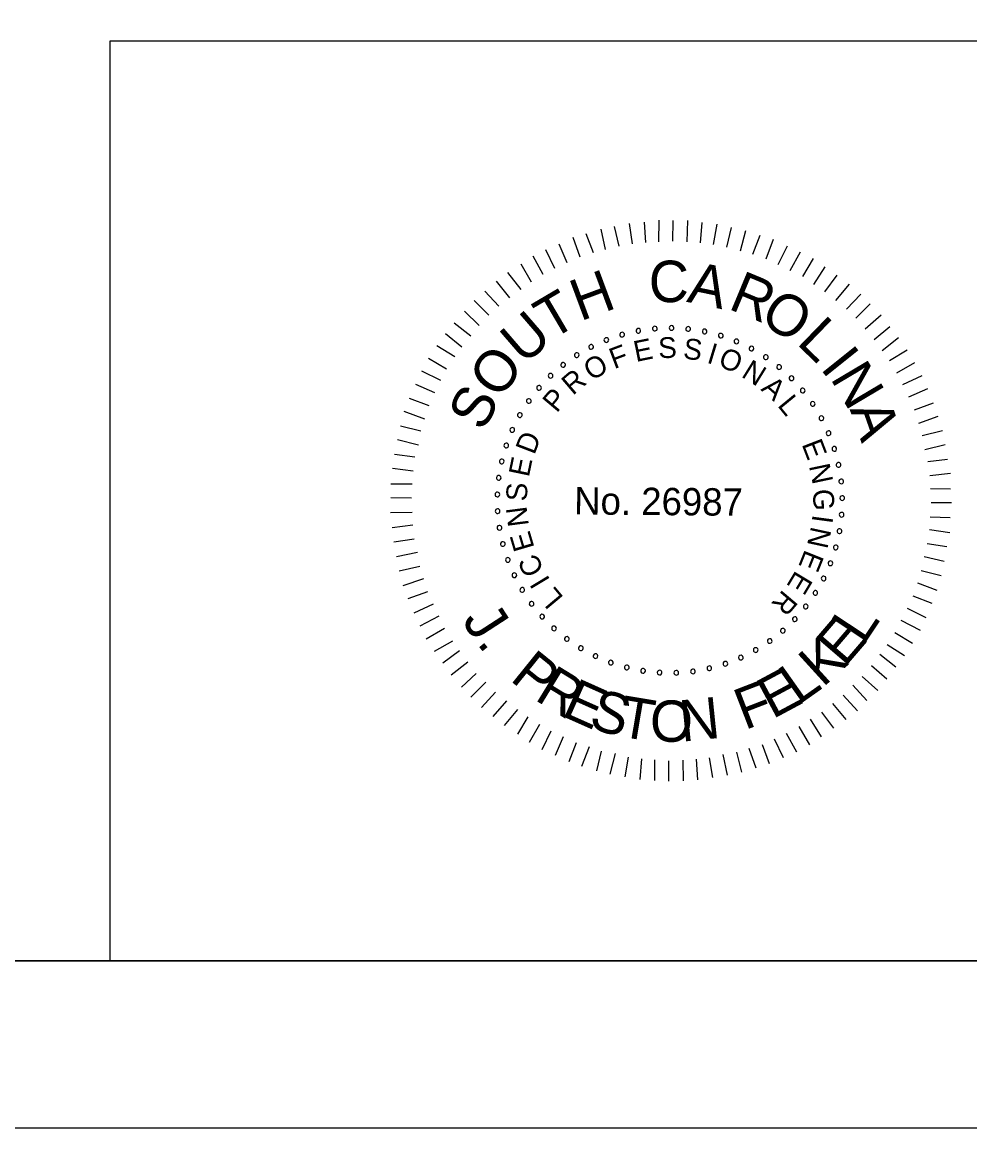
# Model space of a CAD drawing. Extents: x -125.5 to -89.4, y -5.1 to 16.9.
# Drawn here: x -103.162 to -100.328, y -5.066 to -1.76 of the extents above; entities that cross this region are included whole.
import ezdxf

# ---------------------------------------------------------------- set-up
doc = ezdxf.new("R2010")
doc.units = 0
for name, color, linetype in [('BR_BORDER LINES', 7, 'Continuous'), ('BR_TABLE LINES', 7, 'Continuous'), ('BR_TEXT', 7, 'Continuous'), ('Level 31', 7, 'Continuous')]:
    doc.layers.add(name, color=color, linetype=linetype)

msp = doc.modelspace()

# ---------------------------------------------------------------- linework, layer by layer
at = {"layer": 'BR_BORDER LINES'}
for p, q in [((-102.8989, -1.8161), (-97.5337, -1.8161)), ((-102.8989, -4.5661), (-102.8989, -1.8161)), ((-123.6994, -4.5662), (-90.0334, -4.5662))]:
    msp.add_line(p, q, dxfattribs=at)
at = {"layer": 'BR_TABLE LINES'}
msp.add_lwpolyline([(-123.6994, 16.4338), (-90.0334, 16.4338), (-90.0334, -4.5662), (-123.6994, -4.5662)], close=True, dxfattribs=at)
at = {"layer": 'BR_TEXT'}
for p, q in [((-101.418, -2.4404), (-101.4312, -2.3793)), ((-101.3767, -2.4304), (-101.3908, -2.3711)), ((-101.3372, -2.423), (-101.3461, -2.362)), ((-101.2977, -2.419), (-101.3015, -2.3581)), ((-101.2582, -2.4168), (-101.2576, -2.3524)), ((-101.2161, -2.4146), (-101.2156, -2.3528)), ((-101.1741, -2.4175), (-101.1718, -2.3531)), ((-101.1338, -2.4204), (-101.129, -2.3595)), ((-101.0952, -2.425), (-101.0844, -2.3642)), ((-101.0549, -2.4331), (-101.0407, -2.374)), ((-101.4937, -2.4629), (-101.5147, -2.4044)), ((-101.4541, -2.4504), (-101.476, -2.3927)), ((-101.0138, -2.4437), (-100.9979, -2.3829)), ((-100.977, -2.4543), (-100.9551, -2.397)), ((-100.9376, -2.4675), (-100.9157, -2.4093)), ((-101.5695, -2.4966), (-101.5957, -2.4406)), ((-101.5325, -2.4798), (-101.556, -2.4238)), ((-100.9017, -2.485), (-100.8738, -2.4294)), ((-101.604, -2.5144), (-101.6344, -2.46)), ((-100.8658, -2.5024), (-100.8345, -2.4469)), ((-100.8282, -2.5208), (-100.796, -2.467)), ((-101.6704, -2.5593), (-101.7095, -2.5083)), ((-101.6394, -2.5381), (-101.6698, -2.4838)), ((-100.795, -2.5451), (-100.761, -2.4913)), ((-101.7041, -2.5847), (-101.744, -2.5346)), ((-100.7617, -2.5668), (-100.7252, -2.5165)), ((-100.7293, -2.5928), (-100.6886, -2.5434)), ((-101.7369, -2.6094), (-101.7786, -2.5644)), ((-100.6977, -2.618), (-100.6545, -2.5737)), ((-101.7663, -2.6366), (-101.8106, -2.5925)), ((-100.6697, -2.6456), (-100.6264, -2.6022)), ((-101.7958, -2.6673), (-101.8392, -2.6248)), ((-100.6416, -2.6768), (-100.594, -2.6351)), ((-101.8209, -2.6988), (-101.8704, -2.6598)), ((-100.6144, -2.7088), (-100.5677, -2.6705)), ((-101.8469, -2.732), (-101.8964, -2.6922)), ((-100.5906, -2.7424), (-100.5414, -2.7033)), ((-101.8686, -2.761), (-101.9224, -2.728)), ((-100.5686, -2.7718), (-100.516, -2.7396)), ((-101.893, -2.7977), (-101.9467, -2.7656)), ((-101.9104, -2.8319), (-101.9668, -2.804)), ((-100.5466, -2.8089), (-100.4931, -2.7776)), ((-100.5288, -2.8433), (-100.4711, -2.8164)), ((-101.9279, -2.8687), (-101.9852, -2.8433)), ((-100.5111, -2.8804), (-100.4543, -2.856)), ((-101.9454, -2.9072), (-102.0035, -2.8852)), ((-100.4943, -2.9192), (-100.4374, -2.8982)), ((-101.9577, -2.9474), (-102.0193, -2.9246)), ((-100.4809, -2.9596), (-100.4232, -2.9378)), ((-101.97, -2.9833), (-102.0308, -2.9682)), ((-100.4708, -2.9957), (-100.4107, -2.9816)), ((-101.9772, -3.0253), (-102.0397, -3.0094)), ((-100.4626, -3.0378), (-100.4024, -3.0229)), ((-101.9878, -3.0613), (-102.0487, -3.0531)), ((-100.4543, -3.074), (-100.3951, -3.0667)), ((-101.9925, -3.1024), (-102.0542, -3.0951)), ((-100.4478, -3.1152), (-100.3868, -3.1088)), ((-101.9954, -3.1419), (-102.0597, -3.1414)), ((-100.4464, -3.1547), (-100.3863, -3.1552)), ((-101.9974, -3.183), (-102.06, -3.1825)), ((-100.4442, -3.1959), (-100.3833, -3.1964)), ((-101.9961, -3.226), (-102.0604, -3.2272)), ((-100.4471, -3.2388), (-100.3871, -3.241)), ((-101.9938, -3.2646), (-102.0556, -3.2718)), ((-101.9898, -3.3058), (-102.0509, -3.3148)), ((-100.4492, -3.2774), (-100.3883, -3.2856)), ((-100.4564, -3.3185), (-100.3972, -3.3284)), ((-101.9799, -3.3454), (-102.0426, -3.3586)), ((-100.4653, -3.3579), (-100.4053, -3.3721)), ((-101.9733, -3.3875), (-102.0344, -3.4016)), ((-100.4742, -3.3999), (-100.4143, -3.415)), ((-101.9616, -3.4245), (-102.0236, -3.4454)), ((-100.4848, -3.4367), (-100.4275, -3.4586)), ((-101.95, -3.4632), (-102.0085, -3.4842)), ((-101.9331, -3.5003), (-101.9908, -3.5272)), ((-100.4989, -3.4752), (-100.4424, -3.4971)), ((-101.9162, -3.5364), (-101.9731, -3.566)), ((-100.5163, -3.512), (-100.4599, -3.5399)), ((-100.5346, -3.5479), (-100.4774, -3.5784)), ((-101.8994, -3.5735), (-101.9537, -3.6048)), ((-100.553, -3.5846), (-100.5, -3.6168)), ((-101.8756, -3.6106), (-101.93, -3.6419)), ((-100.5756, -3.6213), (-100.5235, -3.6535)), ((-101.8544, -3.6399), (-101.9045, -3.6764)), ((-100.5981, -3.6503), (-100.5495, -3.6876)), ((-101.829, -3.6736), (-101.8791, -3.7127)), ((-100.6224, -3.6836), (-100.5764, -3.7234)), ((-101.8043, -3.7073), (-101.8485, -3.7481)), ((-101.7754, -3.7333), (-101.8204, -3.7784)), ((-100.6502, -3.7168), (-100.6033, -3.7584)), ((-101.7465, -3.7636), (-101.7889, -3.8095)), ((-100.6787, -3.7423), (-100.6362, -3.7882)), ((-101.714, -3.7895), (-101.7548, -3.8364)), ((-100.7392, -3.7976), (-100.6993, -3.8452)), ((-100.7073, -3.7721), (-100.6648, -3.8188)), ((-101.6808, -3.8156), (-101.7207, -3.8633)), ((-100.772, -3.8231), (-100.7364, -3.8714)), ((-101.6501, -3.8373), (-101.6814, -3.8894)), ((-101.6151, -3.8599), (-101.6464, -3.9137)), ((-100.8393, -3.8663), (-100.808, -3.9206)), ((-100.8057, -3.8443), (-100.7727, -3.8969)), ((-101.5809, -3.8799), (-101.608, -3.9355)), ((-101.5442, -3.8974), (-101.5687, -3.953)), ((-100.8773, -3.8857), (-100.8468, -3.9418)), ((-101.5057, -3.9149), (-101.5276, -3.9713)), ((-101.4663, -3.9272), (-101.4891, -3.9854)), ((-100.9892, -3.9311), (-100.9682, -3.9897)), ((-100.9496, -3.9194), (-100.9286, -3.9763)), ((-100.9135, -3.9026), (-100.8865, -3.9586)), ((-101.4304, -3.9395), (-101.4446, -3.9986)), ((-101.3892, -3.9467), (-101.4044, -4.0084)), ((-101.3499, -3.9582), (-101.3598, -4.0165)), ((-101.3104, -3.9628), (-101.3152, -4.0246)), ((-101.271, -3.9657), (-101.2715, -4.0275)), ((-101.1869, -3.9664), (-101.1857, -4.0282)), ((-101.1466, -3.9642), (-101.1428, -4.026)), ((-101.1079, -3.9602), (-101.098, -4.0186)), ((-101.0675, -3.9494), (-101.0542, -4.0113)), ((-101.0262, -3.9429), (-101.0112, -4.0022)), ((-101.229, -3.9686), (-101.2295, -4.0296))]:
    msp.add_line(p, q, dxfattribs=at)
for centre, start, end in [((-101.3196, -2.6831), 10.6038, 190.6038), ((-101.2702, -2.6764), 5.0653, 185.0653), ((-101.2702, -2.6764), 185.0653, 5.0653), ((-101.2204, -2.6745), 359.5268, 179.5268), ((-101.2204, -2.6745), 179.5268, 359.5268), ((-101.1707, -2.6774), 173.9884, 353.9884), ((-101.1707, -2.6774), 353.9884, 173.9884), ((-101.4153, -2.7106), 21.6807, 201.6807), ((-101.4153, -2.7106), 201.6807, 21.6807), ((-101.3681, -2.6945), 16.1422, 196.1422), ((-101.3681, -2.6945), 196.1422, 16.1422), ((-101.3196, -2.6831), 190.6038, 10.6038), ((-101.1214, -2.6851), 168.4499, 348.4499), ((-101.1214, -2.6851), 348.4499, 168.4499), ((-101.0732, -2.6976), 162.9114, 342.9114), ((-101.0732, -2.6976), 342.9114, 162.9114), ((-101.0263, -2.7146), 337.373, 157.373), ((-101.4607, -2.7311), 27.2191, 207.2191), ((-101.4607, -2.7311), 207.2191, 27.2191), ((-101.0263, -2.7146), 157.373, 337.373), ((-100.9814, -2.736), 151.8345, 331.8345), ((-100.9814, -2.736), 331.8345, 151.8345), ((-101.5039, -2.7559), 32.7576, 212.7576), ((-101.5039, -2.7559), 212.7576, 32.7576), ((-100.9387, -2.7617), 146.2961, 326.2961), ((-100.9387, -2.7617), 326.2961, 146.2961), ((-101.5445, -2.7848), 38.2961, 218.2961), ((-101.5445, -2.7848), 218.2961, 38.2961), ((-100.8987, -2.7914), 140.7576, 320.7576), ((-100.8987, -2.7914), 320.7576, 140.7576), ((-101.5821, -2.8175), 43.8345, 223.8345), ((-101.5821, -2.8175), 223.8345, 43.8345), ((-100.8617, -2.8249), 135.2191, 315.2191), ((-100.8617, -2.8249), 315.2191, 135.2191), ((-101.6164, -2.8536), 49.373, 229.373), ((-101.6164, -2.8536), 229.373, 49.373), ((-100.8282, -2.8617), 129.6807, 309.6807), ((-100.8282, -2.8617), 309.6807, 129.6807), ((-101.6471, -2.8929), 54.9114, 234.9114), ((-101.6471, -2.8929), 234.9114, 54.9114), ((-100.7983, -2.9016), 124.1422, 304.1422), ((-100.7983, -2.9016), 304.1422, 124.1422), ((-101.6738, -2.935), 60.4499, 240.4499), ((-101.6738, -2.935), 240.4499, 60.4499), ((-100.7724, -2.9442), 118.6038, 298.6038), ((-100.7724, -2.9442), 298.6038, 118.6038), ((-101.6964, -2.9794), 65.9884, 245.9884), ((-101.6964, -2.9794), 245.9884, 65.9884), ((-100.7508, -2.9891), 113.0653, 293.0653), ((-100.7508, -2.9891), 293.0653, 113.0653), ((-101.7145, -3.0258), 71.5268, 251.5268), ((-101.7145, -3.0258), 251.5268, 71.5268), ((-100.7336, -3.0359), 107.5268, 287.5268), ((-100.7336, -3.0359), 287.5268, 107.5268), ((-101.7281, -3.0738), 77.0653, 257.0653), ((-101.7281, -3.0738), 257.0653, 77.0653), ((-100.721, -3.0841), 101.9884, 281.9884), ((-100.721, -3.0841), 281.9884, 101.9884), ((-101.737, -3.1228), 82.6038, 262.6038), ((-101.737, -3.1228), 262.6038, 82.6038), ((-100.7131, -3.1333), 96.4499, 276.4499), ((-100.7131, -3.1333), 276.4499, 96.4499), ((-101.7411, -3.1724), 88.1422, 268.1422), ((-101.7411, -3.1724), 268.1422, 88.1422), ((-100.71, -3.183), 90.9114, 270.9114), ((-100.71, -3.183), 270.9114, 90.9114), ((-101.7404, -3.2223), 93.6807, 273.6807), ((-101.7404, -3.2223), 273.6807, 93.6807), ((-100.7118, -3.2328), 85.373, 265.373), ((-100.7118, -3.2328), 265.373, 85.373), ((-101.7349, -3.2718), 99.2191, 279.2191), ((-101.7349, -3.2718), 279.2191, 99.2191), ((-100.7183, -3.2822), 79.8345, 259.8345), ((-100.7183, -3.2822), 259.8345, 79.8345), ((-101.7246, -3.3206), 104.7576, 284.7576), ((-101.7246, -3.3206), 284.7576, 104.7576), ((-100.7295, -3.3308), 74.2961, 254.2961), ((-100.7295, -3.3308), 254.2961, 74.2961), ((-101.7097, -3.3681), 110.2961, 290.2961), ((-101.7097, -3.3681), 290.2961, 110.2961), ((-100.7454, -3.378), 68.7576, 248.7576), ((-100.7454, -3.378), 248.7576, 68.7576), ((-101.6903, -3.414), 115.8345, 295.8345), ((-101.6903, -3.414), 295.8345, 115.8345), ((-100.7658, -3.4235), 63.2191, 243.2191), ((-100.7658, -3.4235), 243.2191, 63.2191), ((-101.6665, -3.4578), 121.373, 301.373), ((-101.6665, -3.4578), 301.373, 121.373), ((-100.7904, -3.4668), 57.6807, 237.6807), ((-100.7904, -3.4668), 237.6807, 57.6807), ((-101.6386, -3.4991), 126.9114, 306.9114), ((-101.6386, -3.4991), 306.9114, 126.9114), ((-100.8192, -3.5075), 52.1422, 232.1422), ((-100.8192, -3.5075), 232.1422, 52.1422), ((-101.6069, -3.5375), 132.4499, 312.4499), ((-101.6069, -3.5375), 312.4499, 132.4499), ((-101.5716, -3.5727), 137.9884, 317.9884), ((-101.5716, -3.5727), 317.9884, 137.9884), ((-100.8517, -3.5452), 46.6038, 226.6038), ((-100.8517, -3.5452), 226.6038, 46.6038), ((-101.5331, -3.6043), 143.5268, 323.5268), ((-101.5331, -3.6043), 323.5268, 143.5268), ((-100.9269, -3.6105), 35.5268, 215.5268), ((-100.8877, -3.5797), 41.0653, 221.0653), ((-100.8877, -3.5797), 221.0653, 41.0653), ((-101.4917, -3.632), 149.0653, 329.0653), ((-101.4917, -3.632), 329.0653, 149.0653), ((-100.9688, -3.6374), 29.9884, 209.9884), ((-100.9688, -3.6374), 209.9884, 29.9884), ((-100.9269, -3.6105), 215.5268, 35.5268), ((-101.4478, -3.6556), 154.6038, 334.6038), ((-101.4478, -3.6556), 334.6038, 154.6038), ((-101.4018, -3.6749), 340.1422, 160.1422), ((-101.0132, -3.6601), 24.4499, 204.4499), ((-101.0132, -3.6601), 204.4499, 24.4499), ((-101.4018, -3.6749), 160.1422, 340.1422), ((-101.3542, -3.6896), 165.6807, 345.6807), ((-101.3542, -3.6896), 345.6807, 165.6807), ((-101.3054, -3.6997), 351.2191, 171.2191), ((-101.3054, -3.6997), 171.2191, 351.2191), ((-101.2559, -3.705), 356.7576, 176.7576), ((-101.2061, -3.7055), 2.2961, 182.2961), ((-101.1564, -3.7012), 7.8345, 187.8345), ((-101.1564, -3.7012), 187.8345, 7.8345), ((-101.1074, -3.6921), 13.373, 193.373), ((-101.1074, -3.6921), 193.373, 13.373), ((-101.0595, -3.6784), 18.9114, 198.9114), ((-101.0595, -3.6784), 198.9114, 18.9114), ((-101.2559, -3.705), 176.7576, 356.7576), ((-101.2061, -3.7055), 182.2961, 2.2961)]:
    msp.add_arc(centre, 0.00701, start, end, dxfattribs=at)
at = {"layer": 'Level 31'}
msp.add_lwpolyline([(-125.5328, 16.9339), (-125.5328, -5.0661), (-89.5328, -5.0661), (-89.5328, 16.9339)], dxfattribs=at)

# ---------------------------------------------------------------- texts
at = {"layer": 'BR_TEXT'}
for s, height, rotation, p in [('C', 0.1241, 359.5482, (-101.2889, -2.5969)), ('H', 0.1241, 20.3637, (-101.4933, -2.6552)), ('A', 0.1241, 348.1981, (-101.1775, -2.5961)), ('R', 0.1241, 337.4344, (-101.0542, -2.616)), ('T', 0.1241, 30.4992, (-101.5812, -2.7128)), ('O', 0.1239, 326.5869, (-100.962, -2.6528)), ('U', 0.1241, 40.8022, (-101.6624, -2.7875)), ('L', 0.1241, 315.9488, (-100.8494, -2.7205)), ('E', 0.0622, 11.4103, (-101.3269, -2.7764)), ('S', 0.0622, 2.208, (-101.2591, -2.7654)), ('S', 0.0622, 352.6608, (-101.1878, -2.7657)), ('O', 0.1241, 52.0267, (-101.7369, -2.8914)), ('F', 0.0622, 20.6127, (-101.392, -2.7981)), ('I', 0.0622, 343.1136, (-101.1175, -2.7777)), ('O', 0.0622, 338.4392, (-101.0841, -2.7878)), ('I', 0.1241, 308.6613, (-100.778, -2.7948)), ('O', 0.0622, 30.8477, (-101.4594, -2.8341)), ('N', 0.0622, 328.2042, (-101.0145, -2.8192)), ('N', 0.1241, 300.7037, (-100.7474, -2.8242)), ('R', 0.0622, 40.3949, (-101.5156, -2.878)), ('A', 0.0622, 318.657, (-100.9555, -2.8592)), ('S', 0.1239, 63.2511, (-101.7823, -2.9871)), ('P', 0.0622, 49.9421, (-101.5636, -2.9306)), ('L', 0.0622, 309.4546, (-100.9057, -2.9066)), ('A', 0.1241, 289.4792, (-100.6882, -2.9172)), ('D', 0.0622, 69.0364, (-101.6306, -3.0559)), ('E', 0.0622, 291.049, (-100.8319, -3.0219)), ('E', 0.0622, 78.2388, (-101.6472, -3.1226)), ('N', 0.0622, 281.8466, (-100.8097, -3.0869)), ('S', 0.0622, 87.786, (-101.6529, -3.1936)), ('No. 26987', 0.08175, 359.5268, (-101.5118, -3.232)), ('G', 0.0622, 272.2995, (-100.7979, -3.1572)), ('N', 0.0622, 97.3332, (-101.6467, -3.2646)), ('I', 0.0622, 262.4084, (-100.7983, -3.231)), ('N', 0.0622, 257.7339, (-100.8028, -3.2656)), ('E', 0.0622, 106.5355, (-101.6297, -3.3312)), ('C', 0.0622, 116.4266, (-101.5998, -3.3987)), ('E', 0.0622, 248.1867, (-100.8209, -3.3346)), ('E', 0.0622, 238.9844, (-100.8488, -3.3973)), ('I', 0.0622, 121.1011, (-101.5818, -3.4285)), ('L', 0.0622, 129.9595, (-101.5411, -3.4807)), ('R', 0.0622, 229.782, (-100.8865, -3.4548)), ('J', 0.1236, 302.9559, (-101.849, -3.5492)), ('E', 0.1236, 49.3639, (-100.703, -3.6911)), ('L', 0.1236, 56.4247, (-100.6455, -3.6233)), ('K', 0.1236, 42.3031, (-100.7683, -3.7512)), ('.', 0.1236, 309.3974, (-101.8049, -3.6172)), ('P', 0.1236, 321.1035, (-101.7065, -3.7264)), ('R', 0.1236, 328.5359, (-101.6332, -3.7844)), ('E', 0.1236, 28.1814, (-100.9186, -3.8452)), ('L', 0.1236, 35.2422, (-100.8406, -3.8028)), ('E', 0.1236, 335.9684, (-101.5531, -3.8325)), ('F', 0.1236, 21.1206, (-101.0013, -3.8776)), ('S', 0.1236, 343.0292, (-101.4718, -3.8682)), ('T', 0.1236, 350.4617, (-101.3821, -3.8947)), ('O', 0.1236, 358.1419, (-101.2867, -3.9097)), ('N', 0.1236, 5.8221, (-101.1902, -3.9118))]:
    msp.add_text(s, height=height, rotation=rotation, dxfattribs=at).set_placement(p)

doc.saveas('drawing.dxf')
